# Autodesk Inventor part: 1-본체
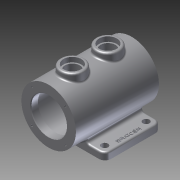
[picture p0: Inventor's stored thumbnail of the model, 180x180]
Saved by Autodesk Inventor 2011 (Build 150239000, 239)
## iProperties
Created: 2014-12
Part Number: 1-본체
Document SubType Name: Modeling
Designer: user
Density: 1 g/cm^3
Author: user
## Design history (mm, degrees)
sketch "스케치1"
  geometry: L1 (-65, -47.5)-(65, -47.5); L2 (65, -47.5)-(65, 47.5); L3 (65, 47.5)-(-65, 47.5); L4 (-65, 47.5)-(-65, -47.5); L5 (-65, -47.5)-(65, 47.5); 2 further points
  constraints: 10 end point, 2 parallel, 1 coincident, 1 horizontal, 1 midpoint, 1 perpendicular
  dimensions: "d0" = 95 distance of L3.end L1.start; "d1" = 130 distance of L2.end L3.end
extrude "돌출1" new body sketch "스케치1" distance "d2" = 12; taper "d3" = 0 deg
node "작업 평면1"
sketch "스케치2"
  geometry: L1 (0, -12)-(130, -12) reference; L2 (130, 0)-(130, -12) reference; L3 (130, 0)-(0, 0) reference; L4 (0, 0)-(0, -12) reference; C1 r 46 at (65, -50); 2 further points
  constraints: 1 centre point, 1 midpoint, 1 vertical alignment
  dimensions: "d5" = 92 diameter of C1; "d6" = 50 distance from line of L3 C1.centre
extrude "돌출2" join sketch "스케치2" distance "d7" = 140; taper "d8" = 0 deg
sketch "스케치3"
  geometry: L1 (-77.5, 96)-(62.5, 96) reference; L2 (62.5, 96)-(62.5, 4) reference; L3 (62.5, 4)-(47.5, 4) reference; L4 (47.5, 4)-(47.5, 0) reference; L5 (47.5, 0)-(-47.5, 0) reference; L6 (-47.5, 0)-(-47.5, 4) reference; L7 (-47.5, 4)-(-77.5, 4) reference; L8 (-77.5, 4)-(-77.5, 96) reference; L9 (-77.5, 50)-(62.5, 50); L10 (-77.5, 80)-(-65.5, 80); L11 (-65.5, 80)-(-65.5, 84.5); L12 (-62.5, 87.5)-(47.5, 87.5); L13 (50.5, 84.5)-(50.5, 80); L14 (50.5, 80)-(62.5, 80); A1 r 3 centre (-62.5, 84.5) between (-62.5, 87.5) and (-65.5, 84.5); A2 r 3 centre (47.5, 84.5) between (50.5, 84.5) and (47.5, 87.5); 1 further point
  constraints: 12 end point, 4 point on circle, 4 tangent, 3 perpendicular, 2 centre point, 2 midpoint, 2 parallel, 2 point on line, 1 equal radius, 1 vertical
  dimensions: "d10" = 60 diameter of L14 L9; "d11" = 60 diameter of L10 L9; "d12" = 75 diameter of L12 L9; "d13" = 12 distance of L13.end L14.end; "d14" = 12 distance of L10.start L10.end; "d15" = 3 radius of A1
revolve "회전1" sketch "스케치3" stored, may be unused: angle "d16" = 90 deg
chamfer "모따기1" distance "d17" = 1; stored, may be unused: second distance "d18" = 2, angle "d19" = 45 deg
node "작업 평면2"
sketch "스케치4"
  geometry: L1 (25.923, -47.5)-(-25.923, -47.5) reference; L2 (-46, 62.5)-(46, 62.5) reference; L3 (46, -77.5)-(-46, -77.5) reference; L4 (25.923, -47.5)-(-25.923, -47.5) reference; L5 (25.923, 47.5)-(25.923, -47.5) reference; L6 (-25.923, 47.5)-(25.923, 47.5) reference; L7 (-25.923, -47.5)-(-25.923, 47.5) reference; C1 r 20 at (0, -37.5); C2 r 20 at (0, 22.5); 1 further point
  constraints: 2 centre point, 2 vertical alignment
  dimensions: "d21" = 40 diameter of C1; "d22" = 40 diameter of C2; "d23" = 40 distance from line of C1.centre L3; "d24" = 40 distance from line of C2.centre L2
extrude "돌출3" join sketch "스케치4" stored distance "d25" = 140; taper "d26" = 0 deg
hole "Hole1" diameter "d29" = 25; stored, may be unused: countersink angle "d33" = 90 deg, drill point angle "d35" = 118 deg; dims "d27" = 10, "d28" = 10, "d30" = 6, "d31" = 30, "d32" = 8, "d34" = 50
hole "Hole2" diameter "d38" = 25; stored, may be unused: countersink angle "d42" = 90 deg, drill point angle "d44" = 118 deg; dims "d36" = 10, "d37" = 10, "d39" = 6, "d40" = 30, "d41" = 8, "d43" = 50
sketch "스케치5"
  geometry: L1 (25.923, 47.5)-(65, 47.5) reference; L2 (25.923, 62.5)-(25.923, 47.5) reference; L3 (25.923, 47.5)-(25.923, -47.5) reference; L4 (65, -47.5)-(25.923, -47.5) reference; L5 (65, 47.5)-(65, -47.5) reference; L6 (25.923, 47.5)-(65, 47.5) reference; L7 (-25.923, 62.5)-(25.923, 62.5) reference; L8 (-25.923, 47.5)-(-25.923, 62.5) reference; L9 (-65, 47.5)-(-25.923, 47.5) reference; L10 (-65, -47.5)-(-65, 47.5) reference; L11 (-25.923, -47.5)-(-65, -47.5) reference; L12 (-25.923, -77.5)-(-25.923, -47.5) reference; L13 (25.923, -77.5)-(-25.923, -77.5) reference; L14 (25.923, -47.5)-(25.923, -77.5) reference; L15 (-25.923, -47.5)-(-25.923, 47.5) reference; L16 (0, 0)-(-6.222, 0); C1 r 5.5 at (-52, 35); C2 r 5.5 at (52, 35); C3 r 5.5 at (52, -35); C4 r 5.5 at (-52, -35)
  constraints: 4 centre point, 2 end point, 2 symmetric about line, 1 horizontal, 2 other
  dimensions: "d45" = 11 diameter of C1; "d46" = 11 diameter of C2; "d47" = 104 distance of C2.centre C1.centre; "d48" = 52 horizontal distance of C2.centre L16.start; "d49" = 12.5 distance from line of C1.centre L9; "d50" = 12.5 distance from line of L1 C2.centre
extrude "돌출4" cut sketch "스케치5" stored distance "d51" = 140; taper "d52" = 0 deg
sketch "스케치6"
  geometry: L1 (0, 0)-(-40, 0); L2 (0, 0)-(-28.284, 28.284); C1 r 31 at (0, 0) reference; 1 further point
  constraints: 4 end point, 1 horizontal
  dimensions: "d53" = 40 distance of L1.start L1.end; "d54" = 40 distance of L1.start L2.end; "d55" = 45 deg angle of L2 L1
hole "Hole3" sketch "스케치6" at (-28.284, 28.284) diameter "d56" = 3.242; stored, may be unused: countersink angle "d60" = 90 deg, drill point angle "d62" = 118 deg; dims "d57" = 8, "d58" = 30, "d59" = 8, "d61" = 10
node "작업 평면3"
sketch "스케치7"
  geometry: L1 (65, 47.5)-(65, -47.5) reference; L2 (53.998, -20.739)-(53.998, 20.739); L3 (53.998, 20.739)-(60.002, 20.739); L4 (60.002, 20.739)-(60.002, -20.739); L5 (60.002, -20.739)-(53.998, -20.739); L6 (53.998, -20.739)-(60.002, 20.739); C1 r 5.5 at (52, -35) reference; 3 further points
  constraints: 2 end point, 1 coincident, 1 midpoint, 2 other
  dimensions: "d67" = 8 distance from line of L1 point (57, 0); "d68" = 35 vertical distance of point (57, 0) C1.centre
feature "엠보싱1" sketch "스케치7" dims "d0" = 95, "d1" = 130, "d69" = 1, "d70" = 0
fillet "모깎기1" dims "d71" = 5
fillet "모깎기2" dims "d72" = 10
fillet "모깎기3" dims "d73" = 3
fillet "모깎기4" dims "d74" = 3
node "솔리드1"
pattern_circular "원형 패턴1" dims angle "d64" = 360 deg
mirror "대칭1"
node "투영된 루프1"
node "투영된 루프2"
node "절단 모서리 투영1"
node "절단 모서리 투영2"
other parameters: "d4" = 15, "d20" = 106
